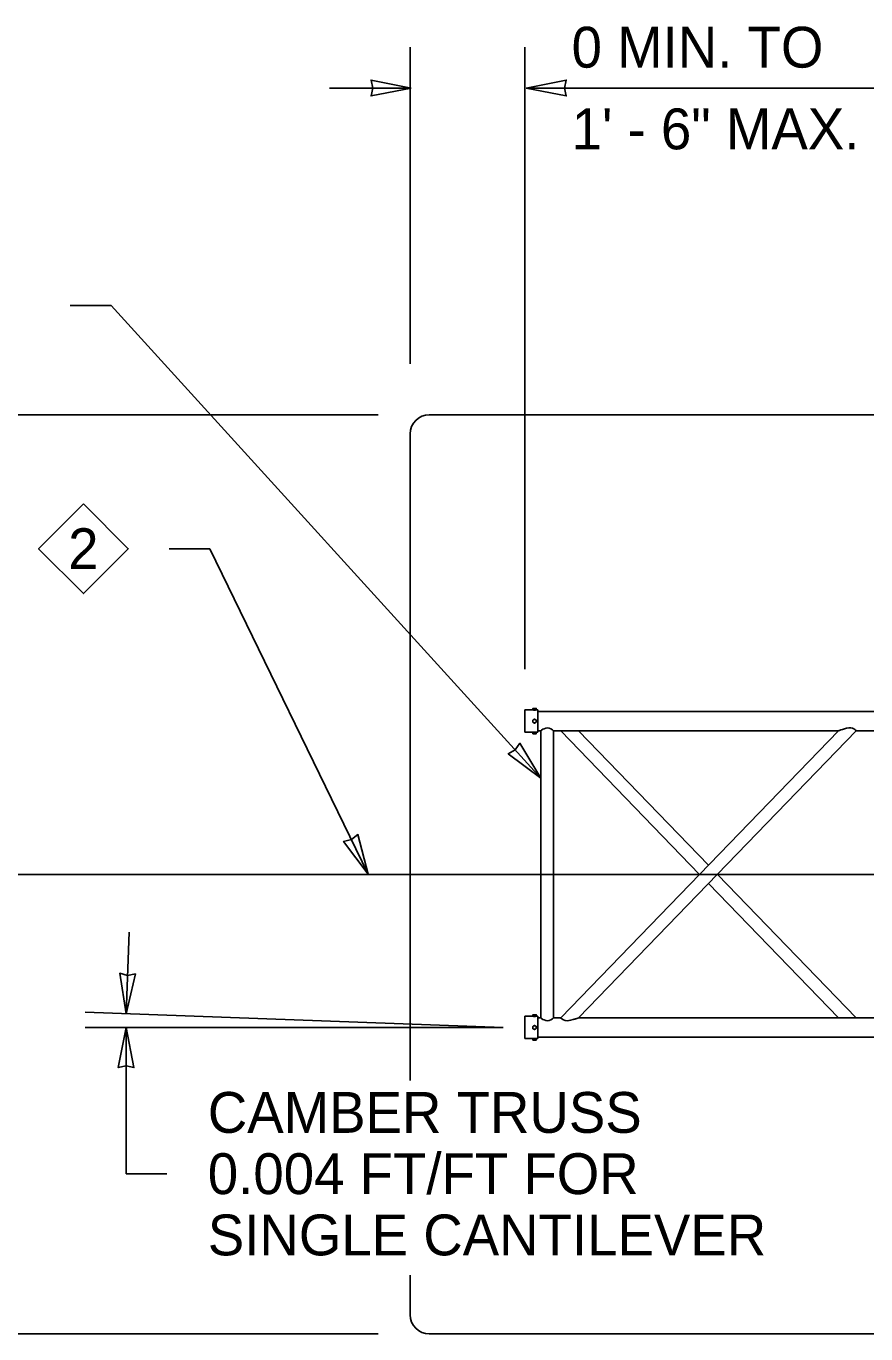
# Model space of a CAD drawing. Extents: x 99862 to 104211, y 98939 to 111076.
# Drawn here: x 100725 to 101054, y 101071 to 101583 of the extents above; entities that cross this region are included whole.
import ezdxf

# ---------------------------------------------------------------- set-up
doc = ezdxf.new("R2010")
doc.units = 0
for name, color, linetype in [('Level 15', 7, 'Continuous'), ('Level 20', 7, 'Continuous'), ('Level 6', 7, 'Continuous'), ('Level 62', 7, 'Continuous'), ('Level 9', 7, 'Continuous')]:
    doc.layers.add(name, color=color, linetype=linetype)

msp = doc.modelspace()

# ---------------------------------------------------------------- linework, layer by layer
at = {"layer": 'Level 15'}
for p, q in [((100875.37, 101451.16), (100875.37, 101575.16)), ((100920.37, 101331.54), (100920.37, 101575.16)), ((100843.81, 101559.16), (100875.81, 101559.16)), ((100920.81, 101559.16), (101062.26, 101559.16)), ((100758.23, 101474.02), (100742.23, 101474.02)), ((100926.62, 101288.78), (100758.23, 101474.02)), ((100862.87, 101431.16), (100625.37, 101431.16)), ((100796.96, 101378.7), (100780.96, 101378.7)), ((100858.92, 101251.22), (100796.96, 101378.7)), ((101165.37, 101251.16), (100695.37, 101251.16)), ((100765.28, 101228.56), (100764.11, 101196.58)), ((100911.88, 101191.16), (100748.12, 101197.16)), ((100911.88, 101191.16), (100748.12, 101191.16)), ((100764.12, 101191.16), (100764.12, 101133.9)), ((100780.12, 101133.9), (100764.12, 101133.9)), ((100862.87, 101071.16), (100625.37, 101071.16))]:
    msp.add_line(p, q, dxfattribs=at)
for points in [[(100875.81, 101559.16), (100860.08, 101556.08), (100860.81, 101559.16), (100860.08, 101562.25)], [(100920.81, 101559.16), (100936.53, 101556.08), (100935.81, 101559.16), (100936.53, 101562.25)], [(100926.62, 101288.78), (100913.81, 101298.4), (100916.59, 101299.92), (100918.39, 101302.52)], [(100858.92, 101251.22), (100849.35, 101264.08), (100852.45, 101264.75), (100854.92, 101266.74)], [(100764.11, 101196.58), (100761.61, 101212.41), (100764.66, 101211.57), (100767.77, 101212.18)], [(100764.12, 101191.16), (100761.04, 101175.44), (100764.12, 101176.17), (100767.21, 101175.44)]]:
    msp.add_lwpolyline(points, close=True, dxfattribs=at)
at = {"layer": 'Level 20'}
msp.add_lwpolyline([(100747.41, 101396.26), (100764.96, 101378.7), (100747.41, 101361.15), (100729.85, 101378.7)], close=True, dxfattribs=at)
at = {"layer": 'Level 6'}
for p, q in [((101467.87, 101431.16), (100882.87, 101431.16)), ((100875.37, 101170.38), (100875.37, 101423.66)), ((100920.37, 101315.54), (100920.37, 101306.79)), ((100920.37, 101315.54), (100923.42, 101315.54)), ((100924.83, 101315.54), (100925.37, 101315.54)), ((100925.37, 101315.54), (100925.37, 101306.79)), ((101808.38, 101314.91), (100925.37, 101314.91)), ((100923.42, 101306.79), (100920.37, 101306.79)), ((100925.37, 101306.79), (100924.83, 101306.79)), ((100926.62, 101307.41), (100925.37, 101307.41)), ((100926.62, 101194.91), (100926.62, 101307.41)), ((100931.62, 101194.91), (100931.62, 101307.41)), ((101043.19, 101307.41), (100931.62, 101307.41)), ((100931.62, 101194.91), (100931.62, 101307.4)), ((100988.79, 101251.16), (100934.39, 101307.41)), ((101043.19, 101307.41), (100934.39, 101194.91)), ((100992.27, 101254.76), (100941.35, 101307.41)), ((101050.14, 101307.41), (100941.35, 101194.91)), ((101057.71, 101307.41), (101050.14, 101307.41)), ((101050.14, 101194.91), (100995.75, 101251.16)), ((101043.19, 101194.91), (100992.27, 101247.57)), ((100920.37, 101195.54), (100920.37, 101186.79)), ((100920.37, 101195.54), (100923.42, 101195.54)), ((100924.83, 101195.54), (100925.37, 101195.54)), ((100925.37, 101195.54), (100925.37, 101186.79)), ((100926.62, 101194.91), (100925.37, 101194.91)), ((100934.4, 101194.91), (100931.62, 101194.91)), ((101166.5, 101194.91), (100941.35, 101194.91)), ((100923.42, 101186.79), (100920.37, 101186.79)), ((100925.37, 101186.79), (100924.83, 101186.79)), ((101808.38, 101187.41), (100925.37, 101187.41)), ((100875.37, 101078.66), (100875.37, 101094.12)), ((101467.87, 101071.16), (100882.87, 101071.16))]:
    msp.add_line(p, q, dxfattribs=at)
for centre, start, end in [((100882.87, 101423.66), 90, 180), ((100882.87, 101078.66), 180, 270)]:
    msp.add_arc(centre, 7.5, start, end, dxfattribs=at)
for points, degree in [([(100923.66, 101315.54), (100923.66, 101315.54), (100923.66, 101315.54), (100923.67, 101315.54), (100923.68, 101315.54), (100923.7, 101315.53), (100923.73, 101315.53), (100923.76, 101315.53), (100923.79, 101315.53), (100923.83, 101315.52), (100923.87, 101315.52), (100923.92, 101315.52), (100923.97, 101315.52), (100924.02, 101315.52), (100924.07, 101315.51), (100924.13, 101315.51), (100924.18, 101315.51), (100924.23, 101315.52), (100924.28, 101315.52), (100924.33, 101315.52), (100924.38, 101315.52), (100924.42, 101315.52), (100924.46, 101315.53), (100924.49, 101315.53), (100924.52, 101315.53), (100924.55, 101315.53), (100924.57, 101315.54), (100924.58, 101315.54), (100924.59, 101315.54), (100924.59, 101315.54), (100924.59, 101315.54)], 3), ([(100924.59, 101306.79), (100924.59, 101306.79), (100924.58, 101306.79), (100924.57, 101306.79), (100924.55, 101306.79), (100924.52, 101306.8), (100924.49, 101306.8), (100924.46, 101306.8), (100924.42, 101306.8), (100924.37, 101306.81), (100924.33, 101306.81), (100924.28, 101306.81), (100924.23, 101306.81), (100924.18, 101306.81), (100924.12, 101306.81), (100924.07, 101306.81), (100924.02, 101306.81), (100923.97, 101306.81), (100923.92, 101306.81), (100923.87, 101306.81), (100923.83, 101306.8), (100923.79, 101306.8), (100923.76, 101306.8), (100923.73, 101306.8), (100923.7, 101306.79), (100923.68, 101306.79), (100923.66, 101306.79), (100923.66, 101306.79), (100923.66, 101306.79), (100923.66, 101306.79), (100923.66, 101306.79)], 3), ([(100931.62, 101307.41), (100931.65, 101307.26), (100929.97, 101309.08), (100926.96, 101307.84), (100926.7, 101307.41), (100926.63, 101307.42), (100926.63, 101307.42), (100926.62, 101307.41)], 3), ([(100926.62, 101307.41), (100926.64, 101307.4), (100926.65, 101307.4), (100926.66, 101307.41)], 2), ([(100931.6, 101307.44), (100931.61, 101307.43), (100931.62, 101307.42), (100931.62, 101307.41), (100931.62, 101307.41)], 3), ([(100934.39, 101307.41), (100934.39, 101307.41), (100934.39, 101307.41), (100934.39, 101307.41)], 2), ([(101043.19, 101307.41), (101043.2, 101307.42), (101044.42, 101307.8), (101048.35, 101309.06), (101050.26, 101307.36), (101050.12, 101307.42), (101050.14, 101307.41)], 3), ([(101050.14, 101307.41), (101050.15, 101307.41), (101050.15, 101307.42), (101050.15, 101307.42)], 2), ([(100923.66, 101195.54), (100923.66, 101195.54), (100923.66, 101195.54), (100923.67, 101195.54), (100923.68, 101195.54), (100923.7, 101195.53), (100923.73, 101195.53), (100923.76, 101195.53), (100923.79, 101195.53), (100923.83, 101195.52), (100923.87, 101195.52), (100923.92, 101195.52), (100923.97, 101195.52), (100924.02, 101195.52), (100924.07, 101195.51), (100924.13, 101195.51), (100924.18, 101195.51), (100924.23, 101195.52), (100924.28, 101195.52), (100924.33, 101195.52), (100924.38, 101195.52), (100924.42, 101195.52), (100924.46, 101195.53), (100924.49, 101195.53), (100924.52, 101195.53), (100924.55, 101195.53), (100924.57, 101195.54), (100924.58, 101195.54), (100924.59, 101195.54), (100924.59, 101195.54), (100924.59, 101195.54)], 3), ([(100931.62, 101194.91), (100931.65, 101195.07), (100929.97, 101193.25), (100926.96, 101194.49), (100926.7, 101194.92), (100926.63, 101194.91), (100926.63, 101194.91), (100926.62, 101194.91)], 3), ([(100926.62, 101194.91), (100926.64, 101194.93), (100926.65, 101194.93), (100926.66, 101194.91)], 2), ([(100931.6, 101194.89), (100931.61, 101194.89), (100931.62, 101194.91), (100931.62, 101194.91), (100931.62, 101194.91)], 3), ([(100934.39, 101194.91), (100934.26, 101194.93), (100936.18, 101193.4), (100939.09, 101194.27), (100940.28, 101194.57), (100940.59, 101194.67), (100940.83, 101194.75), (100941.03, 101194.81), (100941.19, 101194.86), (100941.3, 101194.9), (100941.34, 101194.91), (100941.35, 101194.91), (100941.35, 101194.91), (100941.35, 101194.91)], 3), ([(100934.4, 101194.91), (100934.39, 101194.92), (100934.39, 101194.92), (100934.39, 101194.91)], 2), ([(100941.35, 101194.91), (100941.35, 101194.91), (100941.35, 101194.91), (100941.35, 101194.91)], 2), ([(100924.59, 101186.79), (100924.59, 101186.79), (100924.58, 101186.79), (100924.57, 101186.79), (100924.55, 101186.79), (100924.52, 101186.8), (100924.49, 101186.8), (100924.46, 101186.8), (100924.42, 101186.8), (100924.37, 101186.81), (100924.33, 101186.81), (100924.28, 101186.81), (100924.23, 101186.81), (100924.18, 101186.81), (100924.12, 101186.81), (100924.07, 101186.81), (100924.02, 101186.81), (100923.97, 101186.81), (100923.92, 101186.81), (100923.87, 101186.81), (100923.83, 101186.8), (100923.79, 101186.8), (100923.76, 101186.8), (100923.73, 101186.8), (100923.7, 101186.79), (100923.68, 101186.79), (100923.66, 101186.79), (100923.66, 101186.79), (100923.66, 101186.79), (100923.66, 101186.79), (100923.66, 101186.79)], 3)]:
    msp.add_open_spline(points, degree=degree, dxfattribs=at)
at = {"layer": 'Level 62'}
for points in [[(100924.12, 101306.79), (100924, 101306.79), (100923.87, 101306.8), (100923.79, 101306.8)], [(100924.12, 101186.79), (100924, 101186.79), (100923.87, 101186.8), (100923.79, 101186.8)]]:
    msp.add_open_spline(points, degree=2, dxfattribs=at)
at = {"layer": 'Level 9'}
for p, q in [((100923.42, 101316.16), (100923.76, 101316.16)), ((100923.42, 101316.1), (100923.42, 101315.54)), ((100923.76, 101316.16), (100923.79, 101316.16)), ((100923.79, 101316.16), (100924.46, 101316.16)), ((100924.12, 101316.1), (100924.12, 101315.54)), ((100924.46, 101316.16), (100924.49, 101316.16)), ((100924.49, 101316.16), (100924.83, 101316.16)), ((100924.83, 101316.1), (100924.83, 101315.54)), ((100923.42, 101315.54), (100924.12, 101315.54)), ((100923.76, 101310.56), (100923.79, 101310.55)), ((100924.12, 101315.54), (100924.83, 101315.54)), ((100924.46, 101310.55), (100924.49, 101310.57)), ((100924.48, 101311.77), (100924.47, 101311.78)), ((100924.83, 101311.15), (100924.83, 101311.18)), ((100923.42, 101306.23), (100923.42, 101306.79)), ((100924.12, 101306.79), (100923.42, 101306.79)), ((100923.42, 101306.16), (100924.47, 101306.16)), ((100924.83, 101306.79), (100924.12, 101306.79)), ((100924.12, 101306.23), (100924.12, 101306.79)), ((100924.48, 101306.16), (100924.47, 101306.16)), ((100924.48, 101306.16), (100924.83, 101306.16)), ((100924.83, 101306.23), (100924.83, 101306.79)), ((100923.42, 101196.16), (100923.76, 101196.16)), ((100923.42, 101196.1), (100923.42, 101195.54)), ((100923.42, 101195.54), (100924.12, 101195.54)), ((100923.76, 101196.16), (100923.79, 101196.16)), ((100923.79, 101196.16), (100924.46, 101196.16)), ((100924.12, 101196.1), (100924.12, 101195.54)), ((100924.12, 101195.54), (100924.83, 101195.54)), ((100924.46, 101196.16), (100924.49, 101196.16)), ((100924.49, 101196.16), (100924.83, 101196.16)), ((100924.83, 101196.1), (100924.83, 101195.54)), ((100923.76, 101190.56), (100923.79, 101190.55)), ((100924.46, 101190.55), (100924.49, 101190.57)), ((100924.48, 101191.77), (100924.47, 101191.78)), ((100924.83, 101191.15), (100924.83, 101191.18)), ((100924.12, 101186.79), (100923.42, 101186.79)), ((100923.42, 101186.23), (100923.42, 101186.79)), ((100923.42, 101186.16), (100924.47, 101186.16)), ((100924.83, 101186.79), (100924.12, 101186.79)), ((100924.12, 101186.23), (100924.12, 101186.79)), ((100924.48, 101186.16), (100924.47, 101186.16)), ((100924.48, 101186.16), (100924.83, 101186.16)), ((100924.83, 101186.23), (100924.83, 101186.79))]:
    msp.add_line(p, q, dxfattribs=at)
for centre, start, end in [((100924.12, 101311.16), 60.7554, 180), ((100924.12, 101311.16), 180, 238.8031), ((100924.12, 101311.16), 241.1969, 298.4392), ((100924.12, 101311.16), 1.4168, 59.242), ((100924.12, 101311.16), 301.5608, 358.5832), ((100924.12, 101191.16), 60.7554, 180), ((100924.12, 101191.16), 180, 238.8031), ((100924.12, 101191.16), 241.1969, 298.4392), ((100924.12, 101191.16), 1.4168, 59.242), ((100924.12, 101191.16), 301.5608, 358.5832)]:
    msp.add_arc(centre, 0.703, start, end, dxfattribs=at)
for points, degree in [([(100923.42, 101316.16), (100923.42, 101316.16), (100923.42, 101316.16), (100923.42, 101316.16), (100923.42, 101316.15), (100923.42, 101316.13), (100923.42, 101316.1)], 3), ([(100923.42, 101316.1), (100923.42, 101316.11), (100923.42, 101316.12), (100923.42, 101316.13), (100923.42, 101316.15), (100923.42, 101316.16), (100923.42, 101316.16)], 3), ([(100923.42, 101316.1), (100923.53, 101316.14), (100923.65, 101316.16), (100923.76, 101316.16)], 2), ([(100923.79, 101316.16), (100923.79, 101316.16), (100923.79, 101316.16), (100923.8, 101316.16), (100923.91, 101316.16), (100924.02, 101316.14), (100924.12, 101316.1)], 3), ([(100924.12, 101316.1), (100924.23, 101316.14), (100924.35, 101316.16), (100924.46, 101316.16)], 2), ([(100924.49, 101316.16), (100924.5, 101316.16), (100924.5, 101316.16), (100924.5, 101316.16), (100924.61, 101316.16), (100924.72, 101316.14), (100924.83, 101316.1)], 3), ([(100924.83, 101316.16), (100924.83, 101316.16), (100924.83, 101316.16), (100924.83, 101316.16), (100924.83, 101316.15), (100924.83, 101316.13), (100924.83, 101316.1)], 3), ([(100924.83, 101316.1), (100924.83, 101316.11), (100924.83, 101316.12), (100924.83, 101316.13), (100924.83, 101316.15), (100924.83, 101316.16), (100924.83, 101316.16)], 3), ([(100924.12, 101311.98), (100924, 101311.91), (100923.88, 101311.83), (100923.75, 101311.76), (100923.64, 101311.7), (100923.53, 101311.63), (100923.42, 101311.57)], 3), ([(100923.42, 101311.16), (100923.42, 101311.2), (100923.42, 101311.23), (100923.42, 101311.27), (100923.42, 101311.37), (100923.42, 101311.47), (100923.42, 101311.57)], 3), ([(100923.42, 101310.76), (100923.42, 101310.79), (100923.42, 101310.82), (100923.42, 101310.85), (100923.42, 101310.95), (100923.42, 101311.06), (100923.42, 101311.16)], 3), ([(100923.42, 101310.76), (100923.53, 101310.7), (100923.65, 101310.63), (100923.76, 101310.56)], 2), ([(100923.79, 101310.55), (100923.79, 101310.55), (100923.79, 101310.54), (100923.8, 101310.54), (100923.91, 101310.48), (100924.02, 101310.41), (100924.12, 101310.35)], 3), ([(100924.47, 101311.78), (100924.46, 101311.78), (100924.46, 101311.78), (100924.45, 101311.79), (100924.34, 101311.85), (100924.23, 101311.91), (100924.12, 101311.98)], 3), ([(100924.12, 101310.35), (100924.23, 101310.42), (100924.35, 101310.48), (100924.46, 101310.55)], 2), ([(100924.83, 101311.57), (100924.72, 101311.63), (100924.6, 101311.7), (100924.48, 101311.77)], 2), ([(100924.49, 101310.57), (100924.5, 101310.57), (100924.5, 101310.57), (100924.5, 101310.57), (100924.61, 101310.63), (100924.72, 101310.7), (100924.83, 101310.76)], 3), ([(100924.83, 101311.18), (100924.83, 101311.21), (100924.83, 101311.24), (100924.83, 101311.27), (100924.83, 101311.37), (100924.83, 101311.47), (100924.83, 101311.57)], 3), ([(100924.83, 101310.76), (100924.83, 101310.79), (100924.83, 101310.82), (100924.83, 101310.85), (100924.83, 101310.95), (100924.83, 101311.05), (100924.83, 101311.15)], 3), ([(100923.42, 101306.23), (100923.42, 101306.22), (100923.42, 101306.21), (100923.42, 101306.2), (100923.42, 101306.18), (100923.42, 101306.16), (100923.42, 101306.16)], 3), ([(100923.42, 101306.16), (100923.42, 101306.16), (100923.42, 101306.17), (100923.42, 101306.17), (100923.42, 101306.18), (100923.42, 101306.2), (100923.42, 101306.23)], 3), ([(100924.12, 101306.23), (100924, 101306.19), (100923.88, 101306.16), (100923.75, 101306.16), (100923.64, 101306.17), (100923.53, 101306.19), (100923.42, 101306.23)], 3), ([(100923.79, 101306.16), (100923.79, 101306.16), (100923.79, 101306.16), (100923.79, 101306.16)], 2), ([(100924.47, 101306.16), (100924.46, 101306.16), (100924.46, 101306.16), (100924.45, 101306.16), (100924.34, 101306.17), (100924.23, 101306.19), (100924.12, 101306.23)], 3), ([(100924.83, 101306.23), (100924.72, 101306.19), (100924.6, 101306.17), (100924.48, 101306.16)], 2), ([(100924.83, 101306.23), (100924.83, 101306.22), (100924.83, 101306.21), (100924.83, 101306.2), (100924.83, 101306.18), (100924.83, 101306.17), (100924.83, 101306.16)], 3), ([(100924.83, 101306.16), (100924.83, 101306.16), (100924.83, 101306.17), (100924.83, 101306.17), (100924.83, 101306.18), (100924.83, 101306.2), (100924.83, 101306.23)], 3), ([(100923.42, 101196.16), (100923.42, 101196.16), (100923.42, 101196.16), (100923.42, 101196.16), (100923.42, 101196.15), (100923.42, 101196.13), (100923.42, 101196.1)], 3), ([(100923.42, 101196.1), (100923.42, 101196.11), (100923.42, 101196.12), (100923.42, 101196.13), (100923.42, 101196.15), (100923.42, 101196.16), (100923.42, 101196.16)], 3), ([(100923.42, 101196.1), (100923.53, 101196.14), (100923.65, 101196.16), (100923.76, 101196.16)], 2), ([(100923.79, 101196.16), (100923.79, 101196.16), (100923.79, 101196.16), (100923.8, 101196.16), (100923.91, 101196.16), (100924.02, 101196.14), (100924.12, 101196.1)], 3), ([(100924.12, 101196.1), (100924.23, 101196.14), (100924.35, 101196.16), (100924.46, 101196.16)], 2), ([(100924.49, 101196.16), (100924.5, 101196.16), (100924.5, 101196.16), (100924.5, 101196.16), (100924.61, 101196.16), (100924.72, 101196.14), (100924.83, 101196.1)], 3), ([(100924.83, 101196.16), (100924.83, 101196.16), (100924.83, 101196.16), (100924.83, 101196.16), (100924.83, 101196.15), (100924.83, 101196.13), (100924.83, 101196.1)], 3), ([(100924.83, 101196.1), (100924.83, 101196.11), (100924.83, 101196.12), (100924.83, 101196.13), (100924.83, 101196.15), (100924.83, 101196.16), (100924.83, 101196.16)], 3), ([(100924.12, 101191.98), (100924, 101191.91), (100923.88, 101191.83), (100923.75, 101191.76), (100923.64, 101191.7), (100923.53, 101191.63), (100923.42, 101191.57)], 3), ([(100923.42, 101191.16), (100923.42, 101191.2), (100923.42, 101191.23), (100923.42, 101191.27), (100923.42, 101191.37), (100923.42, 101191.47), (100923.42, 101191.57)], 3), ([(100923.42, 101190.76), (100923.42, 101190.79), (100923.42, 101190.82), (100923.42, 101190.85), (100923.42, 101190.95), (100923.42, 101191.06), (100923.42, 101191.16)], 3), ([(100923.42, 101190.76), (100923.53, 101190.7), (100923.65, 101190.63), (100923.76, 101190.56)], 2), ([(100923.79, 101190.55), (100923.79, 101190.55), (100923.79, 101190.54), (100923.8, 101190.54), (100923.91, 101190.48), (100924.02, 101190.41), (100924.12, 101190.35)], 3), ([(100924.47, 101191.78), (100924.46, 101191.78), (100924.46, 101191.78), (100924.45, 101191.79), (100924.34, 101191.85), (100924.23, 101191.91), (100924.12, 101191.98)], 3), ([(100924.12, 101190.35), (100924.23, 101190.42), (100924.35, 101190.48), (100924.46, 101190.55)], 2), ([(100924.83, 101191.57), (100924.72, 101191.63), (100924.6, 101191.7), (100924.48, 101191.77)], 2), ([(100924.49, 101190.57), (100924.5, 101190.57), (100924.5, 101190.57), (100924.5, 101190.57), (100924.61, 101190.63), (100924.72, 101190.7), (100924.83, 101190.76)], 3), ([(100924.83, 101191.18), (100924.83, 101191.21), (100924.83, 101191.24), (100924.83, 101191.27), (100924.83, 101191.37), (100924.83, 101191.47), (100924.83, 101191.57)], 3), ([(100924.83, 101190.76), (100924.83, 101190.79), (100924.83, 101190.82), (100924.83, 101190.85), (100924.83, 101190.95), (100924.83, 101191.05), (100924.83, 101191.15)], 3), ([(100923.42, 101186.23), (100923.42, 101186.22), (100923.42, 101186.21), (100923.42, 101186.2), (100923.42, 101186.18), (100923.42, 101186.16), (100923.42, 101186.16)], 3), ([(100923.42, 101186.16), (100923.42, 101186.16), (100923.42, 101186.17), (100923.42, 101186.17), (100923.42, 101186.18), (100923.42, 101186.2), (100923.42, 101186.23)], 3), ([(100924.12, 101186.23), (100924, 101186.19), (100923.88, 101186.16), (100923.75, 101186.16), (100923.64, 101186.17), (100923.53, 101186.19), (100923.42, 101186.23)], 3), ([(100923.79, 101186.16), (100923.79, 101186.16), (100923.79, 101186.16), (100923.79, 101186.16)], 2), ([(100924.47, 101186.16), (100924.46, 101186.16), (100924.46, 101186.16), (100924.45, 101186.16), (100924.34, 101186.17), (100924.23, 101186.19), (100924.12, 101186.23)], 3), ([(100924.83, 101186.23), (100924.72, 101186.19), (100924.6, 101186.17), (100924.48, 101186.16)], 2), ([(100924.83, 101186.23), (100924.83, 101186.22), (100924.83, 101186.21), (100924.83, 101186.2), (100924.83, 101186.18), (100924.83, 101186.17), (100924.83, 101186.16)], 3), ([(100924.83, 101186.16), (100924.83, 101186.16), (100924.83, 101186.17), (100924.83, 101186.17), (100924.83, 101186.18), (100924.83, 101186.2), (100924.83, 101186.23)], 3)]:
    msp.add_open_spline(points, degree=degree, dxfattribs=at)

# ---------------------------------------------------------------- texts
at = {"layer": 'Level 20'}
for s, p in [('0 MIN. TO', (100938.65, 101567.16)), ('1\' - 6" MAX.', (100938.65, 101535.16)), ('2', (100741.42, 101370.71))]:
    msp.add_text(s, height=16, dxfattribs=at).set_placement(p)
for s, p in [('CAMBER TRUSS', (100796.12, 101149.9)), ('0.004 FT/FT FOR ', (100796.12, 101125.9)), ('SINGLE CANTILEVER', (100796.12, 101101.9))]:
    msp.add_text(s, height=16, rotation=360, dxfattribs=at).set_placement(p)

doc.saveas('drawing.dxf')
